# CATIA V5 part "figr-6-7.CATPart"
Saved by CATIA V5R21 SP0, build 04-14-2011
Part number: Part1
Bounding box of the stored display mesh (mm): x -62.5 to 62.5, y -75 to 75, z 0 to 20
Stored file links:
  D:\CATIA V5R21 E-RESOURCES\CATIA-V5R21\catia-v5r21-prt\c06-catia-v5r21-prt\c06-catia-v5r21-figr-6-7.CATPart
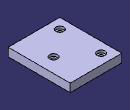
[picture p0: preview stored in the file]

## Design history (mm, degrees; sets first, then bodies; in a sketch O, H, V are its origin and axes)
Body1 (main body)
  Sketch1 on xy-plane, origin (0, 0, 0), H (1, 0, 0), V (0, 1, 0)
    line L1 (-62.5, 75) -> (62.5, 75)
    line L2 (62.5, 75) -> (62.5, -75)
    line L3 (62.5, -75) -> (-62.5, -75)
    line L4 (-62.5, -75) -> (-62.5, 75)
    axis line L5 (62.5, -75) -> (-62.5, 75)
    length L2 = 150
    length L3 = 125
    horizontal: L1 H, L3 H
    vertical: L2 V, L4 V
    midpoint: O L5
  Pad1: profile Sketch1, direction (0, 0, 1), length 20
  Sketch2 on face of Pad1, origin (-40.5285, -55.3052, 20), H (1, 0, 0), V (0, 1, 0)
    point P1 (3.0285, 5.3052)
    reference projected line E1 (-21.9715, -19.6948) -> (103.0285, -19.6948) from edge [face of Pad1 | face of Pad1]
    reference projected line E2 (-21.9715, 130.3052) -> (-21.9715, -19.6948) from edge [face of Pad1 | face of Pad1]
    distance P1 E1 = 25
    distance P1 E2 = 25
  Hole1: placed by Sketch2, at (-37.5, -50, 20) direction (0, 0, -1), diameter 11, through (limit type 3), counterbore diameter 19, counterbore depth 6
  Sketch3 on face of Pad1, origin (-46.6283, 59.6815, 20), H (1, 0, 0), V (0, 1, 0)
    point P1 (9.1283, -9.6815)
    reference projected line E1 (-15.8717, 15.3185) -> (-15.8717, -134.6815) from edge [face of Pad1 | face of Pad1]
    reference projected line E2 (109.1283, 15.3185) -> (-15.8717, 15.3185) from edge [face of Pad1 | face of Pad1]
    distance P1 E1 = 25
    distance P1 E2 = 25
  Hole2: placed by Sketch3, at (-37.5, 50, 20) direction (0, 0, -1), diameter 11, through (limit type 3), counterbore diameter 19, counterbore depth 6
  Sketch4 on face of Pad1, origin (29.7716, -8.2192, 20), H (1, 0, 0), V (0, 1, 0)
    point P1 (-2.2716, 8.2192)
    reference projected line E1 (-92.2716, -66.7808) -> (32.7284, -66.7808) from edge [face of Pad1 | face of Pad1]
    reference projected line E2 (32.7284, -66.7808) -> (32.7284, 83.2192) from edge [face of Pad1 | face of Pad1]
    distance P1 E1 = 75
    distance P1 E2 = 35
  Hole3: placed by Sketch4, at (27.5, 0, 20) direction (0, 0, -1), diameter 11, through (limit type 3), counterbore diameter 19, counterbore depth 6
